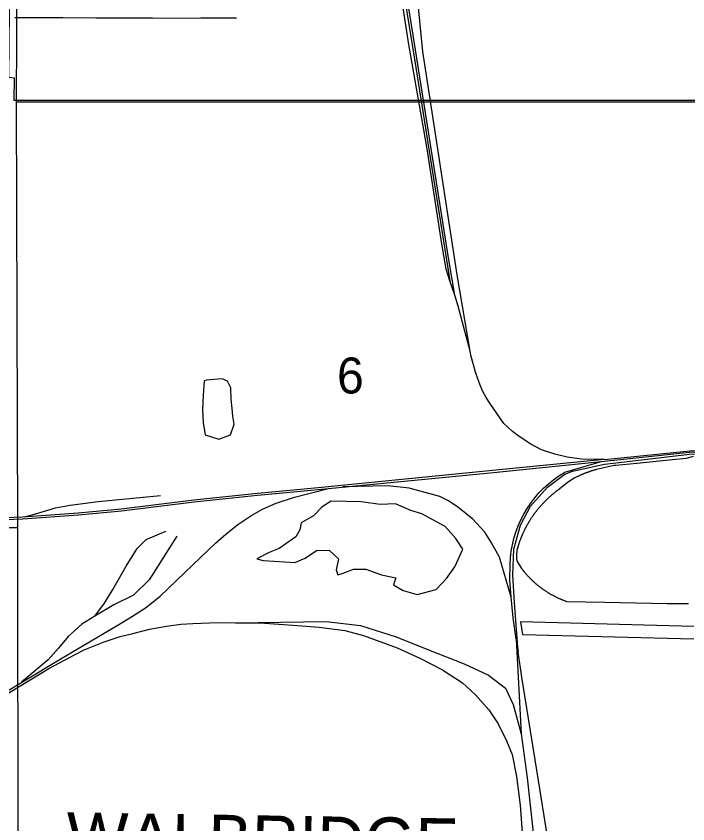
# Model space of a CAD drawing. Extents: x 0 to 40.2, y 0 to 22.
# Drawn here: x 2.955 to 3.735, y 15.414 to 16.354 of the extents above; entities that cross this region are included whole.
import ezdxf

# ---------------------------------------------------------------- set-up
doc = ezdxf.new("R2010")
doc.units = 0
for name, color, linetype in [('GM_X_City_Street', 7, 'Continuous'), ('GM_X_Corporation', 7, 'Continuous'), ('GM_X_County_Road_Text', 7, 'Continuous'), ('GM_X_Major_River', 7, 'Continuous'), ('GM_X_Minor_Lake_Text', 7, 'Continuous'), ('GM_X_Unincorporated_Location', 7, 'Continuous')]:
    doc.layers.add(name, color=color, linetype=linetype)

msp = doc.modelspace()

# ---------------------------------------------------------------- linework, layer by layer
at = {"layer": 'GM_X_Corporation'}
for points in [[(2.96218, 17.25819), (3.76422, 17.2609), (3.77479, 16.25485), (3.74559, 16.25368), (2.95497, 16.25386), (2.95786, 16.79166)], [(2.1, 16.80277), (2.1, 15.76442), (2.95674, 15.75847), (2.95497, 16.25386), (2.95786, 16.79166), (2.43037, 16.80164), (2.18336, 16.80457)], [(2.95497, 16.25386), (3.74559, 16.25368), (3.74809, 15.33567), (2.9569, 15.35216), (2.95674, 15.75847)], [(2.1, 15.76442), (2.1, 14.73705), (2.95186, 14.72799), (2.9569, 15.35216), (2.95674, 15.75847)]]:
    msp.add_lwpolyline(points, close=True, dxfattribs=at)
for points in [[(2.94777, 16.47691), (2.94574, 16.28254), (2.95227, 16.28186), (2.95199, 16.25577), (3.76676, 16.25602)], [(3.74151, 15.84134), (3.73345, 15.83891), (3.71786, 15.83745), (3.67636, 15.8333), (3.65161, 15.83091), (3.64992, 15.83074), (3.62942, 15.82618), (3.62868, 15.82597), (3.62829, 15.82587), (3.62758, 15.82567), (3.62683, 15.82546), (3.62609, 15.82527), (3.62506, 15.82495), (3.62432, 15.82472), (3.6236, 15.82449), (3.62321, 15.82437), (3.62249, 15.82413), (3.62177, 15.8239), (3.62105, 15.82365), (3.62069, 15.82352), (3.61998, 15.82327), (3.61962, 15.82314), (3.61925, 15.82302), (3.6189, 15.82289), (3.61854, 15.82275), (3.61817, 15.82262), (3.61781, 15.82249), (3.61745, 15.82236), (3.61709, 15.82222), (3.61673, 15.82208), (3.61637, 15.82194), (3.61567, 15.82167), (3.61531, 15.82152), (3.61495, 15.82138), (3.61425, 15.8211), (3.61389, 15.82096), (3.61319, 15.82066), (3.61283, 15.82052), (3.61214, 15.82021), (3.61178, 15.82006), (3.61107, 15.81977), (3.61038, 15.81946), (3.60968, 15.81914), (3.60931, 15.81899), (3.60864, 15.81867), (3.60828, 15.81851), (3.60761, 15.81819), (3.60725, 15.81802), (3.60657, 15.81769), (3.60587, 15.81737), (3.60553, 15.81719), (3.60485, 15.81685), (3.60416, 15.81651), (3.60382, 15.81633), (3.60348, 15.81615), (3.60314, 15.81598), (3.6028, 15.8158), (3.59799, 15.81263), (3.59522, 15.8106), (3.59084, 15.80721), (3.58803, 15.80483), (3.58772, 15.80461), (3.58741, 15.8044), (3.58679, 15.80395), (3.58648, 15.80373), (3.58616, 15.8035), (3.58555, 15.80306), (3.58494, 15.80261), (3.58463, 15.80238), (3.58402, 15.80193), (3.58341, 15.80147), (3.58309, 15.80125), (3.58251, 15.80076), (3.58219, 15.80054), (3.58161, 15.80007), (3.58099, 15.7996), (3.58041, 15.79912), (3.57982, 15.79864), (3.57923, 15.79816), (3.57865, 15.79767), (3.57806, 15.79718), (3.57777, 15.79693), (3.57748, 15.79668), (3.57718, 15.79643), (3.57662, 15.79593), (3.57632, 15.79568), (3.57576, 15.79518), (3.57547, 15.79493), (3.5749, 15.79442), (3.57434, 15.7939), (3.57405, 15.79365), (3.57351, 15.79314), (3.57321, 15.79288), (3.57267, 15.79235), (3.57238, 15.79209), (3.57183, 15.79157), (3.5713, 15.79104), (3.57103, 15.79076), (3.57049, 15.79024), (3.56994, 15.7897), (3.5694, 15.78916), (3.56914, 15.78889), (3.56861, 15.78834), (3.56834, 15.78806), (3.56807, 15.78779), (3.56755, 15.78724), (3.56704, 15.78669), (3.56677, 15.78641), (3.56651, 15.78612), (3.566, 15.78558), (3.56575, 15.78529), (3.56548, 15.78502), (3.56523, 15.78472), (3.56499, 15.78444), (3.56446, 15.78388), (3.56422, 15.78359), (3.56397, 15.7833), (3.56372, 15.78302), (3.56348, 15.78273), (3.56323, 15.78244), (3.56298, 15.78215), (3.56274, 15.78187), (3.56249, 15.78156), (3.56224, 15.78128), (3.56177, 15.78069), (3.56153, 15.78041), (3.56127, 15.7801), (3.5608, 15.77952), (3.56033, 15.77892), (3.55986, 15.77833), (3.55939, 15.77773), (3.55914, 15.77743), (3.55869, 15.77683), (3.55847, 15.77652), (3.55821, 15.77622), (3.55777, 15.77562), (3.55732, 15.77501), (3.55687, 15.7744), (3.55665, 15.77408), (3.55619, 15.77348), (3.55577, 15.77285), (3.55555, 15.77253), (3.55512, 15.77191), (3.5549, 15.7716), (3.55447, 15.77098), (3.55405, 15.77035), (3.55382, 15.77004), (3.55342, 15.7694), (3.55319, 15.76909), (3.55279, 15.76845), (3.55239, 15.76781), (3.55219, 15.76749), (3.55179, 15.76685), (3.55158, 15.76653), (3.55138, 15.7662), (3.55098, 15.76556), (3.55078, 15.76523), (3.5504, 15.76458), (3.5502, 15.76426), (3.54982, 15.7636), (3.54962, 15.76328), (3.54944, 15.76295), (3.54906, 15.76229), (3.54886, 15.76196), (3.54851, 15.76131), (3.5483, 15.76097), (3.54795, 15.76031), (3.54759, 15.75964), (3.54741, 15.7593), (3.54723, 15.75897), (3.54688, 15.7583), (3.5467, 15.75797), (3.54652, 15.75763), (3.54619, 15.75696), (3.54601, 15.75662), (3.54567, 15.75594), (3.5455, 15.75561), (3.54532, 15.75526), (3.54501, 15.75458), (3.54484, 15.75424), (3.54468, 15.7539), (3.54434, 15.75322), (3.54404, 15.75253), (3.54388, 15.75218), (3.5437, 15.75185), (3.54355, 15.75149), (3.54324, 15.7508), (3.54309, 15.75046), (3.5428, 15.74977), (3.54264, 15.74942), (3.54236, 15.74872), (3.5422, 15.74837), (3.54191, 15.74768), (3.54134, 15.74627), (3.54106, 15.74556), (3.5408, 15.74486), (3.5405, 15.74416), (3.54038, 15.7438), (3.54011, 15.74309), (3.53998, 15.74273), (3.53972, 15.74203), (3.53948, 15.74132), (3.53922, 15.7406), (3.53898, 15.73989), (3.53887, 15.73953), (3.53863, 15.73881), (3.5385, 15.73845), (3.53829, 15.73774), (3.53816, 15.73737), (3.53684, 15.73197), (3.53626, 15.72685), (3.53649, 15.72271), (3.53684, 15.7198), (3.54232, 15.71098), (3.54255, 15.71068), (3.543, 15.71009), (3.54324, 15.70978), (3.54348, 15.70948), (3.54393, 15.70889), (3.54417, 15.70859), (3.5444, 15.7083), (3.54464, 15.708), (3.54488, 15.70771), (3.54511, 15.70741), (3.54538, 15.70712), (3.54561, 15.70682), (3.54585, 15.70653), (3.54632, 15.70596), (3.54682, 15.70538), (3.54732, 15.70482), (3.54782, 15.70425), (3.54831, 15.70368), (3.54858, 15.70339), (3.54907, 15.70283), (3.54959, 15.70228), (3.55012, 15.70172), (3.55064, 15.70118), (3.5509, 15.7009), (3.55142, 15.70035), (3.55194, 15.69981), (3.55248, 15.69927), (3.55301, 15.69874), (3.55355, 15.69821), (3.55409, 15.69769), (3.55464, 15.69716), (3.55493, 15.69691), (3.55547, 15.69638), (3.55604, 15.69588), (3.55659, 15.69537), (3.55687, 15.6951), (3.55744, 15.69461), (3.55772, 15.69435), (3.55829, 15.69385), (3.55886, 15.69336), (3.55946, 15.69287), (3.56002, 15.69238), (3.56033, 15.69215), (3.5609, 15.69166), (3.56149, 15.69118), (3.56208, 15.69071), (3.56267, 15.69024), (3.56299, 15.69), (3.56358, 15.68954), (3.56389, 15.68931), (3.56448, 15.68885), (3.56479, 15.68863), (3.56509, 15.68841), (3.5654, 15.68818), (3.56571, 15.68795), (3.56632, 15.68751), (3.56663, 15.68729), (3.56694, 15.68707), (3.56756, 15.68664), (3.56817, 15.6862), (3.56881, 15.68578), (3.56943, 15.68535), (3.57007, 15.68493), (3.5704, 15.68472), (3.57102, 15.68431), (3.57166, 15.6839), (3.57229, 15.6835), (3.57263, 15.6833), (3.57327, 15.6829), (3.5736, 15.6827), (3.57424, 15.6823), (3.57457, 15.68212), (3.5749, 15.68193), (3.57523, 15.68173), (3.57557, 15.68153), (3.5759, 15.68135), (3.57654, 15.68098), (3.57687, 15.68079), (3.57754, 15.68043), (3.57787, 15.68024), (3.57855, 15.67988), (3.57922, 15.67951), (3.57988, 15.67916), (3.58057, 15.67882), (3.58124, 15.67847), (3.58158, 15.6783), (3.58225, 15.67797), (3.58294, 15.67763), (3.58363, 15.6773), (3.58431, 15.67698), (3.58499, 15.67666), (3.58535, 15.67651), (3.58604, 15.67619), (3.5864, 15.67603), (3.58708, 15.67572), (3.58744, 15.67558), (3.5878, 15.67543), (3.58848, 15.67513), (3.58884, 15.67499), (3.58919, 15.67484), (3.58955, 15.6747), (3.5899, 15.67456), (3.59026, 15.67441), (3.59095, 15.67414), (3.59166, 15.67387), (3.59201, 15.67373), (3.59272, 15.67347), (3.5931, 15.67333), (3.59381, 15.67306), (3.59453, 15.67282), (3.63857, 15.67179), (3.71132, 15.6705), (3.73174, 15.67026), (3.73618, 15.67016)], [(3.74233, 15.64371), (3.54101, 15.64902), (3.54332, 15.63428), (3.74237, 15.62917)]]:
    msp.add_lwpolyline(points, dxfattribs=at)
at = {"layer": 'GM_X_Major_River'}
for p, q in [((3.46453, 16.02883), (3.45889, 16.04586)), ((3.53608, 15.62892), (3.54157, 15.51864))]:
    msp.add_line(p, q, dxfattribs=at)
for points in [[(3.46453, 16.02883), (3.45736, 16.07244), (3.41778, 16.32183), (3.3959, 16.45734), (3.35966, 16.67492)], [(3.45889, 16.04586), (3.45447, 16.05919), (3.44916, 16.09104), (3.43268, 16.19922), (3.41132, 16.32073), (3.39288, 16.43952), (3.3737, 16.5572), (3.35938, 16.64813), (3.35952, 16.66083)], [(3.35952, 16.66083), (3.41783, 16.30366), (3.45889, 16.04586)], [(3.63879, 15.83803), (3.61181, 15.83815), (3.5953, 15.84062), (3.58101, 15.84385), (3.56551, 15.84894), (3.55219, 15.85599), (3.538, 15.86557), (3.53181, 15.87053), (3.52165, 15.87981), (3.50517, 15.90333), (3.50107, 15.91012), (3.49737, 15.91713), (3.49409, 15.92436), (3.49124, 15.93176), (3.48883, 15.93932), (3.48311, 15.95923), (3.48236, 15.96374), (3.46748, 16.05254), (3.42749, 16.31236), (3.42143, 16.37549)], [(3.48236, 15.96374), (3.46866, 16.01637), (3.46453, 16.02883)], [(3.31787, 15.804), (3.5059, 15.8224), (3.64969, 15.83717), (3.74092, 15.84664), (3.80393, 15.8452), (3.85329, 15.83714), (3.91713, 15.81674), (4.02063, 15.77692), (4.24133, 15.6946)], [(3.63854, 15.83233), (3.74108, 15.84425), (3.80371, 15.84226), (3.85268, 15.8349), (3.91636, 15.81455), (4.01984, 15.77474), (4.2425, 15.69144), (4.27856, 15.67922), (4.29452, 15.67367), (4.3278, 15.66215)], [(3.63879, 15.83803), (3.74168, 15.84848), (3.80378, 15.84797), (3.85389, 15.83938), (3.91791, 15.81893), (4.02142, 15.7791), (4.08684, 15.75547)], [(3.31761, 15.80631), (3.50834, 15.82532), (3.63805, 15.83822), (3.63879, 15.83803)], [(3.53032, 15.67783), (3.52865, 15.69742), (3.52906, 15.71595), (3.52946, 15.72355), (3.53031, 15.73113), (3.53161, 15.73863), (3.53337, 15.74605), (3.53556, 15.75334), (3.53819, 15.76049), (3.54125, 15.76747), (3.54472, 15.77426), (3.54858, 15.78082), (3.55284, 15.78714), (3.55746, 15.79319), (3.56244, 15.79896), (3.56776, 15.80442), (3.5734, 15.80954), (3.57933, 15.81432), (3.58554, 15.81874), (3.592, 15.82277), (3.59243, 15.82302), (3.63626, 15.83579)], [(3.53608, 15.62892), (3.5383, 15.61394), (3.53404, 15.6715), (3.53193, 15.70314), (3.53335, 15.73366), (3.5409, 15.76151), (3.5527, 15.78347), (3.57251, 15.80565), (3.59271, 15.82062), (3.60162, 15.82426), (3.63854, 15.83233)], [(2.1, 15.78256), (2.41111, 15.77776), (2.47365, 15.77642), (2.7481, 15.7691), (2.86744, 15.76821), (2.90983, 15.7691), (2.96246, 15.77114), (3.02699, 15.77592), (3.0768, 15.78058), (3.16141, 15.79096), (3.23516, 15.79872), (3.28544, 15.80337), (3.31766, 15.80631)], [(3.53032, 15.67783), (3.51652, 15.72423), (3.50724, 15.74071), (3.49937, 15.75323), (3.48538, 15.76888), (3.46812, 15.78227), (3.45727, 15.78992), (3.44716, 15.79479), (3.41138, 15.80455), (3.38662, 15.80729), (3.33462, 15.80586)], [(2.1, 15.78024), (2.41107, 15.77544), (2.47359, 15.7741), (2.74806, 15.76678), (2.86745, 15.76589), (2.9099, 15.76678), (2.96259, 15.76882), (3.02718, 15.77361), (3.07705, 15.77828), (3.16167, 15.78865), (3.23539, 15.79641), (3.28565, 15.80106), (3.31787, 15.804)], [(2.73307, 15.44158), (3.00774, 15.60692), (3.07593, 15.64698), (3.09014, 15.65567), (3.10501, 15.66541), (3.11383, 15.67212), (3.12225, 15.67896), (3.15989, 15.71489), (3.18687, 15.74082), (3.19833, 15.75109), (3.21241, 15.76241), (3.22754, 15.77228), (3.2411, 15.77991), (3.25702, 15.78689), (3.27821, 15.79412), (3.31787, 15.804)], [(2.96441, 15.77128), (2.97881, 15.77502), (3.00051, 15.78159), (3.01761, 15.78488), (3.05016, 15.78883), (3.1225, 15.79606)], [(3.04626, 15.65549), (3.05761, 15.67078), (3.06698, 15.68656), (3.08276, 15.71369), (3.09559, 15.7344), (3.10594, 15.74476), (3.12863, 15.75462)], [(3.14146, 15.74871), (3.1094, 15.69791), (3.09115, 15.68015), (3.06846, 15.66881), (3.04626, 15.65549)], [(3.53608, 15.62892), (3.53239, 15.65379), (3.53032, 15.67783)], [(3.04626, 15.65549), (3.03098, 15.64612), (3.01519, 15.63181), (3.00385, 15.6185), (2.99201, 15.60469), (2.97524, 15.59088), (2.96083, 15.57868)], [(2.73307, 15.44158), (2.76006, 15.45365), (2.99281, 15.59457), (3.02351, 15.61101), (3.03378, 15.61623), (3.05722, 15.62588), (3.07561, 15.63176), (3.0905, 15.63553), (3.1098, 15.64031), (3.12938, 15.64389), (3.14629, 15.64619), (3.16008, 15.6472), (3.18922, 15.64831), (3.20966, 15.648)], [(3.20966, 15.648), (3.31492, 15.64941), (3.35503, 15.64481), (3.39646, 15.63166), (3.43395, 15.61653), (3.47538, 15.60009), (3.50366, 15.58694), (3.52338, 15.57181), (3.53259, 15.55274), (3.54157, 15.51864)], [(3.20966, 15.648), (3.24382, 15.64748), (3.28196, 15.6449), (3.30687, 15.64279), (3.33683, 15.63902), (3.35853, 15.63314), (3.3976, 15.61889), (3.42416, 15.60667), (3.45036, 15.59315), (3.47361, 15.5779), (3.48878, 15.5642), (3.50404, 15.54674), (3.51507, 15.53037), (3.52481, 15.5107), (3.53143, 15.49471), (3.53621, 15.46897), (3.54051, 15.43589), (3.54308, 15.4041)], [(3.69269, 14.1), (3.68307, 14.30316), (3.65685, 14.76254), (3.6489, 14.90626), (3.64294, 14.9554), (3.62561, 15.07071), (3.60317, 15.20676), (3.58187, 15.33798), (3.56398, 15.45245), (3.54267, 15.58452), (3.5383, 15.61394)], [(3.54157, 15.51864), (3.5488, 15.46735), (3.55538, 15.40751), (3.55538, 15.40441)]]:
    msp.add_lwpolyline(points, dxfattribs=at)
at = {"layer": 'GM_X_Minor_Lake_Text'}
for p, q in [((3.20644, 15.8882), (3.2058, 15.89731)), ((3.42632, 15.77462), (3.41353, 15.77858))]:
    msp.add_line(p, q, dxfattribs=at)
for points in [[(3.2058, 15.89731), (3.20481, 15.90795), (3.20422, 15.92124), (3.20055, 15.92888), (3.19416, 15.93161), (3.17601, 15.93032), (3.17335, 15.92922), (3.172, 15.91216), (3.1714, 15.89585), (3.17197, 15.88104), (3.17442, 15.86659), (3.19022, 15.86146), (3.20389, 15.8666), (3.20821, 15.87907), (3.20644, 15.8882)], [(3.41353, 15.77858), (3.3955, 15.78639), (3.37774, 15.78548), (3.35586, 15.78841), (3.32074, 15.78923), (3.31046, 15.78291), (3.3005, 15.77241), (3.28604, 15.76424), (3.28441, 15.75591), (3.27978, 15.748), (3.26033, 15.73421), (3.24894, 15.7298), (3.23449, 15.72238), (3.24202, 15.72039), (3.25447, 15.71948), (3.27863, 15.71804), (3.29079, 15.7232), (3.30375, 15.73214), (3.31848, 15.73234), (3.32931, 15.72233), (3.32687, 15.70946), (3.32869, 15.70375), (3.33475, 15.70557), (3.34691, 15.71035), (3.36126, 15.71017), (3.37931, 15.70349), (3.39626, 15.70024), (3.39351, 15.69192), (3.40476, 15.68533), (3.42094, 15.68095), (3.44293, 15.68675), (3.45481, 15.6995), (3.46481, 15.71304), (3.47414, 15.73341), (3.466, 15.74604), (3.45333, 15.75986), (3.42632, 15.77462)]]:
    msp.add_lwpolyline(points, dxfattribs=at)
at = {"layer": 'GM_X_Unincorporated_Location'}
msp.add_lwpolyline([(2.95318, 16.35193), (2.95825, 16.35192), (2.97535, 16.35186), (3.00891, 16.35186), (3.04748, 16.35163), (3.06303, 16.35162), (3.08851, 16.35144), (3.11335, 16.35155), (3.12949, 16.35128), (3.16929, 16.35149), (3.19233, 16.35152), (3.211, 16.35144)], dxfattribs=at)

# ---------------------------------------------------------------- texts
at = {"layer": 'GM_X_City_Street'}
msp.add_text('6', height=0.04186, rotation=0.00001, dxfattribs=at).set_placement((3.32769, 15.91462))
at = {"layer": 'GM_X_County_Road_Text'}
msp.add_text('WALBRIDGE', height=0.056818, rotation=359.08373, dxfattribs=at).set_placement((3.01297, 15.37065))

doc.saveas('drawing.dxf')
